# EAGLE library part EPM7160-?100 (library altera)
EPM7160E MAX 7000 family
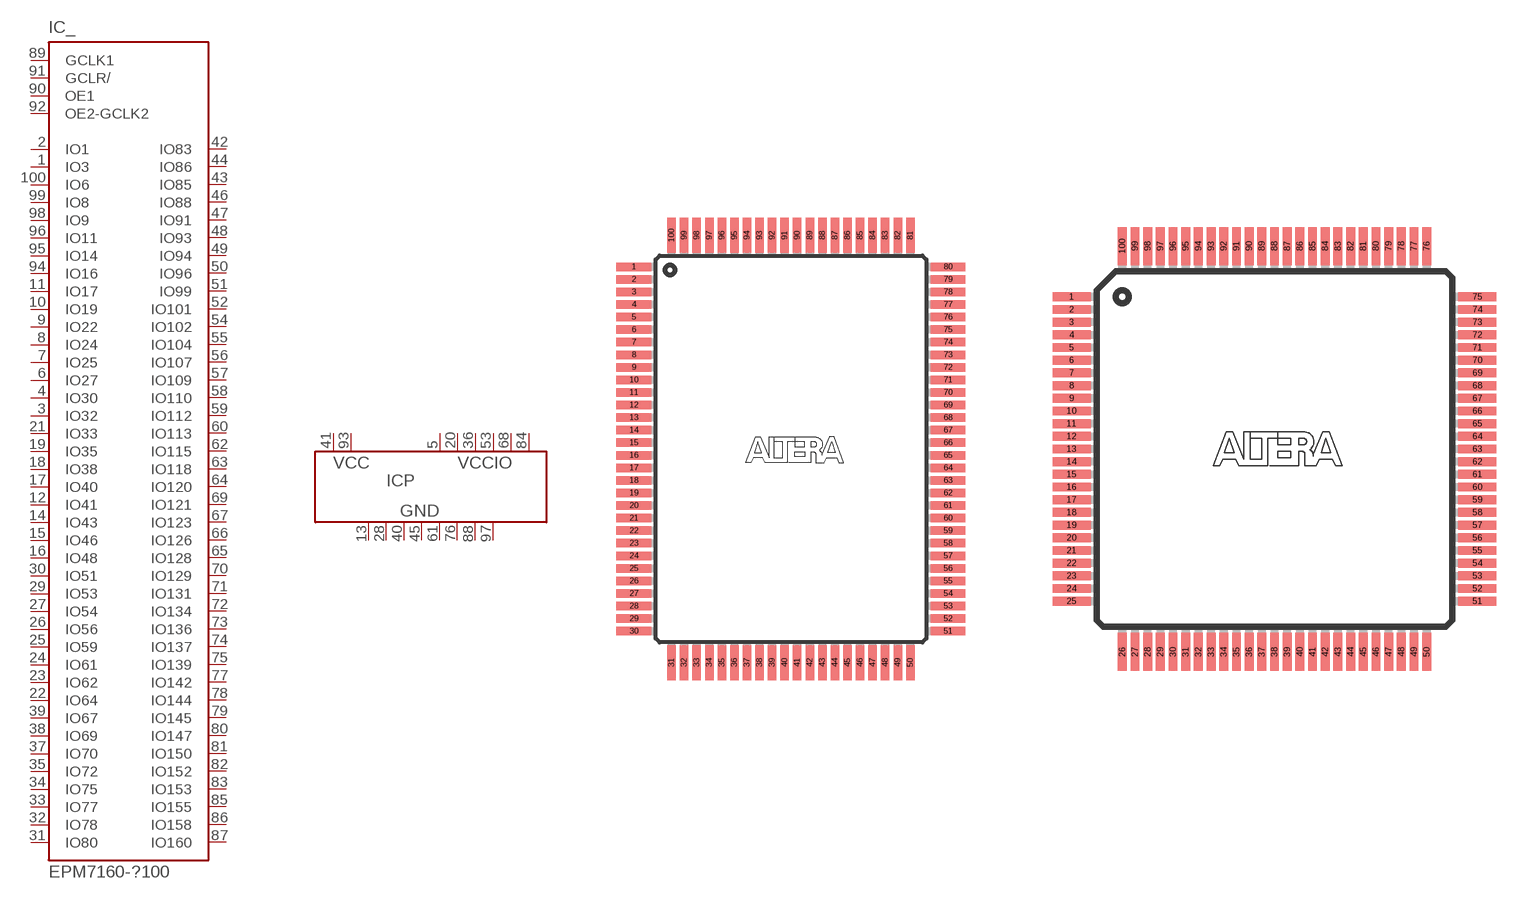
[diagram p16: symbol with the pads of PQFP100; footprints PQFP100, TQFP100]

Designator prefix IC; gates _=7160P100 P=PWR8-2-6

## EPM7160-P100 (MPN: EPM7160SQC160-10N; OC_FARNELL: 1549437; OC_NEWARK: 51R9800)  [PQFP100]
1  _:IO3
2  _:IO1
3  _:IO32
4  _:IO30
5  P:VCCIO  pwr
6  _:IO27
7  _:IO25
8  _:IO24
9  _:IO22
10  _:IO19
11  _:IO17
12  _:IO41
13  P:GND  pwr
14  _:IO43
15  _:IO46
16  _:IO48
17  _:IO40
18  _:IO38
19  _:IO35
20  P:VCCIO  pwr
21  _:IO33
22  _:IO64
23  _:IO62
24  _:IO61
25  _:IO59
26  _:IO56
27  _:IO54
28  P:GND  pwr
29  _:IO53
30  _:IO51
31  _:IO80
32  _:IO78
33  _:IO77
34  _:IO75
35  _:IO72
36  P:VCCIO  pwr
37  _:IO70
38  _:IO69
39  _:IO67
40  P:GND  pwr
41  P:VCC  pwr
42  _:IO83
43  _:IO85
44  _:IO86
45  P:GND  pwr
46  _:IO88
47  _:IO91
48  _:IO93
49  _:IO94
50  _:IO96
51  _:IO99
52  _:IO101
53  P:VCCIO  pwr
54  _:IO102
55  _:IO104
56  _:IO107
57  _:IO109
58  _:IO110
59  _:IO112
60  _:IO113
61  P:GND  pwr
62  _:IO115
63  _:IO118
64  _:IO120
65  _:IO128
66  _:IO126
67  _:IO123
68  P:VCCIO  pwr
69  _:IO121
70  _:IO129
71  _:IO131
72  _:IO134
73  _:IO136
74  _:IO137
75  _:IO139
76  P:GND  pwr
77  _:IO142
78  _:IO144
79  _:IO145
80  _:IO147
81  _:IO150
82  _:IO152
83  _:IO153
84  P:VCCIO  pwr
85  _:IO155
86  _:IO158
87  _:IO160
88  P:GND  pwr
89  _:GCLK1  in
90  _:OE1  in
91  _:GCLR/  in
92  _:OE2-GCLK2  in
93  P:VCC  pwr
94  _:IO16
95  _:IO14
96  _:IO11
97  P:GND  pwr
98  _:IO9
99  _:IO8
100  _:IO6

## EPM7160-T100 (MPN: EPM7160STC100-10N; OC_FARNELL: 1549429; OC_NEWARK: 51R9804)  [TQFP100]
1  _:IO32
2  _:IO30
3  P:VCCIO  pwr
4  _:IO27
5  _:IO25
6  _:IO24
7  _:IO22
8  _:IO19
9  _:IO17
10  _:IO41
11  P:GND  pwr
12  _:IO43
13  _:IO46
14  _:IO48
15  _:IO40
16  _:IO38
17  _:IO35
18  P:VCCIO  pwr
19  _:IO33
20  _:IO64
21  _:IO62
22  _:IO61
23  _:IO59
24  _:IO56
25  _:IO54
26  P:GND  pwr
27  _:IO53
28  _:IO51
29  _:IO80
30  _:IO78
31  _:IO77
32  _:IO75
33  _:IO72
34  P:VCCIO  pwr
35  _:IO70
36  _:IO69
37  _:IO67
38  P:GND  pwr
39  P:VCC  pwr
40  _:IO83
41  _:IO85
42  _:IO86
43  P:GND  pwr
44  _:IO88
45  _:IO91
46  _:IO93
47  _:IO94
48  _:IO96
49  _:IO99
50  _:IO101
51  P:VCCIO  pwr
52  _:IO102
53  _:IO104
54  _:IO107
55  _:IO109
56  _:IO110
57  _:IO112
58  _:IO113
59  P:GND  pwr
60  _:IO115
61  _:IO118
62  _:IO120
63  _:IO128
64  _:IO126
65  _:IO123
66  P:VCCIO  pwr
67  _:IO121
68  _:IO129
69  _:IO131
70  _:IO134
71  _:IO136
72  _:IO137
73  _:IO139
74  P:GND  pwr
75  _:IO142
76  _:IO144
77  _:IO145
78  _:IO147
79  _:IO150
80  _:IO152
81  _:IO153
82  P:VCCIO  pwr
83  _:IO155
84  _:IO158
85  _:IO160
86  P:GND  pwr
87  _:GCLK1  in
88  _:OE1  in
89  _:GCLR/  in
90  _:OE2-GCLK2  in
91  P:VCC  pwr
92  _:IO16
93  _:IO14
94  _:IO11
95  P:GND  pwr
96  _:IO9
97  _:IO8
98  _:IO6
99  _:IO3
100  _:IO1

## Footprint PQFP100 (pad centres in mm)
Plastic Quad Flat Pack
smd 1.8 x 0.44: 1 -8.125,9.425; 2 -8.125,8.775; 3 -8.125,8.125; 4 -8.125,7.475; 5 -8.125,6.825; 6 -8.125,6.175; 7 -8.125,5.525; 8 -8.125,4.875; 9 -8.125,4.225; 10 -8.125,3.575; 11 -8.125,2.925; 12 -8.125,2.275; 13 -8.125,1.625; 14 -8.125,0.975; 15 -8.125,0.325; 16 -8.125,-0.325; 17 -8.125,-0.975; 18 -8.125,-1.625; 19 -8.125,-2.275; 20 -8.125,-2.925; 21 -8.125,-3.575; 22 -8.125,-4.225; 23 -8.125,-4.875; 24 -8.125,-5.525; 25 -8.125,-6.175; 26 -8.125,-6.825; 27 -8.125,-7.475; 28 -8.125,-8.125; 29 -8.125,-8.775; 30 -8.125,-9.425; 51 8.125,-9.425; 52 8.125,-8.775; 53 8.125,-8.125; 54 8.125,-7.475; 55 8.125,-6.825; 56 8.125,-6.175; 57 8.125,-5.525; 58 8.125,-4.875; 59 8.125,-4.225; 60 8.125,-3.575; 61 8.125,-2.925; 62 8.125,-2.275; 63 8.125,-1.625; 64 8.125,-0.975; 65 8.125,-0.325; 66 8.125,0.325; 67 8.125,0.975; 68 8.125,1.625; 69 8.125,2.275; 70 8.125,2.925; 71 8.125,3.575; 72 8.125,4.225; 73 8.125,4.875; 74 8.125,5.525; 75 8.125,6.175; 76 8.125,6.825; 77 8.125,7.475; 78 8.125,8.125; 79 8.125,8.775; 80 8.125,9.425
smd 0.44 x 1.8: 31 -6.175,-11.05; 32 -5.525,-11.05; 33 -4.875,-11.05; 34 -4.225,-11.05; 35 -3.575,-11.05; 36 -2.925,-11.05; 37 -2.275,-11.05; 38 -1.625,-11.05; 39 -0.975,-11.05; 40 -0.325,-11.05; 41 0.325,-11.05; 42 0.975,-11.05; 43 1.625,-11.05; 44 2.275,-11.05; 45 2.925,-11.05; 46 3.575,-11.05; 47 4.225,-11.05; 48 4.875,-11.05; 49 5.525,-11.05; 50 6.175,-11.05; 81 6.175,11.05; 82 5.525,11.05; 83 4.875,11.05; 84 4.225,11.05; 85 3.575,11.05; 86 2.925,11.05; 87 2.275,11.05; 88 1.625,11.05; 89 0.975,11.05; 90 0.325,11.05; 91 -0.325,11.05; 92 -0.975,11.05; 93 -1.625,11.05; 94 -2.275,11.05; 95 -2.925,11.05; 96 -3.575,11.05; 97 -4.225,11.05; 98 -4.875,11.05; 99 -5.525,11.05; 100 -6.175,11.05

## Footprint TQFP100 (pad centres in mm)
Plastic Thin Quad Flat Pack
smd 1.5 x 0.35: 1 -8,6; 2 -8,5.5; 3 -8,5; 4 -8,4.5; 5 -8,4; 6 -8,3.5; 7 -8,3; 8 -8,2.5; 9 -8,2; 10 -8,1.5; 11 -8,1; 12 -8,0.5; 13 -8,0; 14 -8,-0.5; 15 -8,-1; 16 -8,-1.5; 17 -8,-2; 18 -8,-2.5; 19 -8,-3; 20 -8,-3.5; 21 -8,-4; 22 -8,-4.5; 23 -8,-5; 24 -8,-5.5; 25 -8,-6; 51 8,-6; 52 8,-5.5; 53 8,-5; 54 8,-4.5; 55 8,-4; 56 8,-3.5; 57 8,-3; 58 8,-2.5; 59 8,-2; 60 8,-1.5; 61 8,-1; 62 8,-0.5; 63 8,0; 64 8,0.5; 65 8,1; 66 8,1.5; 67 8,2; 68 8,2.5; 69 8,3; 70 8,3.5; 71 8,4; 72 8,4.5; 73 8,5; 74 8,5.5; 75 8,6
smd 0.35 x 1.5: 26 -6,-8; 27 -5.5,-8; 28 -5,-8; 29 -4.5,-8; 30 -4,-8; 31 -3.5,-8; 32 -3,-8; 33 -2.5,-8; 34 -2,-8; 35 -1.5,-8; 36 -1,-8; 37 -0.5,-8; 38 0,-8; 39 0.5,-8; 40 1,-8; 41 1.5,-8; 42 2,-8; 43 2.5,-8; 44 3,-8; 45 3.5,-8; 46 4,-8; 47 4.5,-8; 48 5,-8; 49 5.5,-8; 50 6,-8; 76 6,8; 77 5.5,8; 78 5,8; 79 4.5,8; 80 4,8; 81 3.5,8; 82 3,8; 83 2.5,8; 84 2,8; 85 1.5,8; 86 1,8; 87 0.5,8; 88 0,8; 89 -0.5,8; 90 -1,8; 91 -1.5,8; 92 -2,8; 93 -2.5,8; 94 -3,8; 95 -3.5,8; 96 -4,8; 97 -4.5,8; 98 -5,8; 99 -5.5,8; 100 -6,8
